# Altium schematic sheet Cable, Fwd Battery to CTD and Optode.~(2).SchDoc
size Tabloid; Organization: Monterey Bay Aquarium Research Institute; Address1: 7700 Sandholdt Rd; Address2: Moss Landing, CA 95039-9644; CompanyName: MBARI; PageSetup: Record=PageOptions|CenterHorizontal=True|CenterVertical=True|PrintScale=1.00|XCorrection=1.00|YCorrection=1.00|PrintKind=0|BorderSize=5000000|LeftOffset=0|BottomOffset=0|Orientation=2|PaperLength=1000|PaperWidth=1000|Scale=100|PaperSource=7|PrintQuality=-4|MediaType=1|DitherType=10|PaperKind=Letter|PrintScaleMode=1
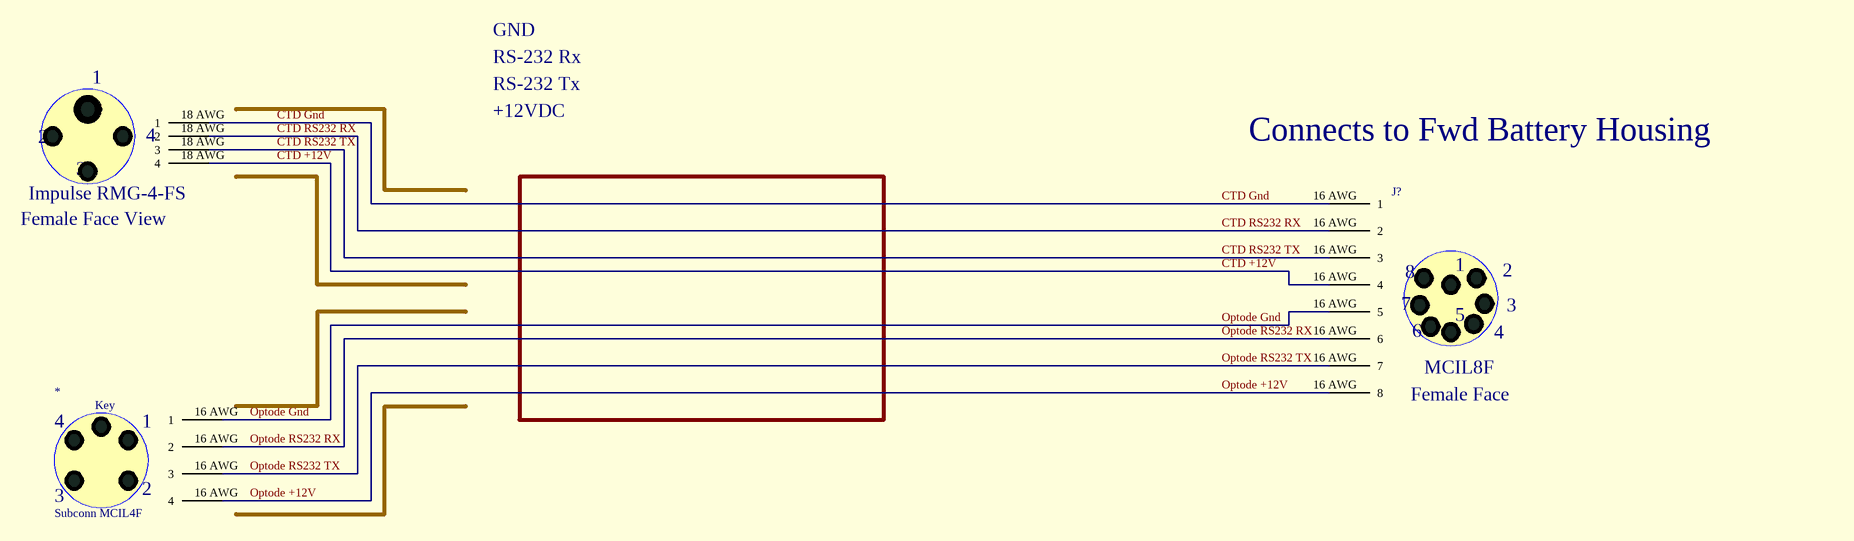
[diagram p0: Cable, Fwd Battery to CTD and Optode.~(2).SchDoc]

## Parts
*  Subconn MCIL4F
?  Impulse RMG-4-FS  [None Available]
J?  MCIL8F  View: Female Face

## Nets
CTD +12V: ?.18_AWG(4) J?.16_AWG(4)
CTD Gnd: ?.18_AWG(1) J?.16_AWG(1)
CTD RS232 RX: ?.18_AWG(2) J?.16_AWG(2)
CTD RS232 TX: ?.18_AWG(3) J?.16_AWG(3)
Optode +12V: *.16_AWG(4) J?.16_AWG(8)
Optode Gnd: *.16_AWG(1) J?.16_AWG(5)
Optode RS232 RX: *.16_AWG(2) J?.16_AWG(6)
Optode RS232 TX: *.16_AWG(3) J?.16_AWG(7)

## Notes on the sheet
- GND
- RS-232 Rx
- RS-232 Tx
- +12VDC
- Connects to Fwd Battery Housing
- Female Face View

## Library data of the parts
* = Subconn MCIL4F: Subconn MCIL4F Connector
? = IMPULSE-RMG-4-FS-REVERSE
J? = SUBCONN-MCxx8F: Subconn MCIL8F Connector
